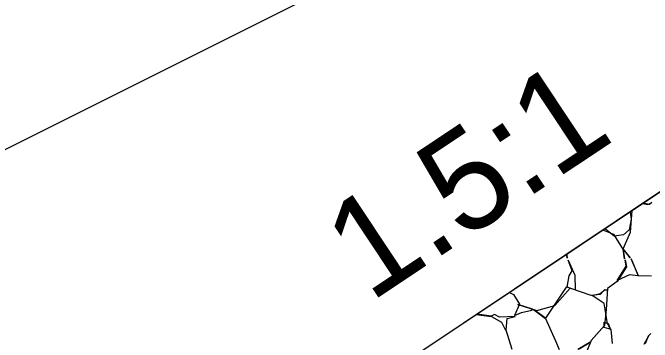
# Model space of a CAD drawing. Extents: x -26 to 2998798, y -429 to 819149.
# Drawn here: x 251.89 to 258.31, y 2039.34 to 2042.64 of the extents above; entities that cross this region are included whole.
import ezdxf

# ---------------------------------------------------------------- set-up
doc = ezdxf.new("R2010")
doc.units = 0
for name, color, linetype in [('DESIGN - EARTHWORK - Shapes', 7, 'Continuous'), ('DESIGN - PROFILE - Patterning', 7, 'Continuous'), ('DESIGN - SCRATCH - User 2', 7, 'Continuous'), ('DESIGN - SCRATCH - User 3', 7, 'Continuous'), ('DESIGN - SCRATCH - User 4', 7, 'Continuous'), ('DESIGN - TYPICAL - Finished Grade and Subgrade', 7, 'Continuous'), ('DESIGN - TYPICAL - Finished Grade Slopes Text', 7, 'Continuous')]:
    doc.layers.add(name, color=color, linetype=linetype)

msp = doc.modelspace()

# ---------------------------------------------------------------- linework, layer by layer
at = {"layer": 'DESIGN - EARTHWORK - Shapes'}
msp.add_lwpolyline([(300, 2056.0783), (299.2449, 2056.0632), (289, 2055.8583), (280.6596, 2055.6915), (236.27, 2026.0985), (247.7146, 2028.6577), (250.1042, 2028.9885), (255.4266, 2030.1126), (263.9312, 2032.5208), (268.2871, 2033.7542), (277.5839, 2036.1115), (286.7578, 2039.5231), (290.5851, 2040.9483), (292.2962, 2041.3689), (299.2394, 2040.0629), (300, 2040.0056)], dxfattribs=at)
at = {"layer": 'DESIGN - PROFILE - Patterning'}
for points in [[(258.2138, 2040.7276), (258.2669, 2040.7195), (258.3069, 2040.7395), (258.2819, 2040.7195), (258.22, 2040.7318)], [(257.8143, 2040.4613), (257.8369, 2040.4545), (257.9219, 2040.4195), (258.0169, 2040.2645), (258.0319, 2040.1745), (258.0169, 2040.2695), (258.0869, 2040.1845), (258.0169, 2040.2745), (258.0919, 2040.4395), (258.1094, 2040.6581)], [(258.0864, 2040.6427), (258.0969, 2040.5695), (258.0769, 2040.4645), (258.0219, 2040.4145), (257.9269, 2040.3995), (257.8419, 2040.4695), (257.8301, 2040.4719)], [(257.4481, 2040.2172), (257.4519, 2040.2145), (257.4569, 2040.1795), (257.4519, 2040.2095), (257.4454, 2040.2154)], [(257.9119, 2039.3245), (257.8969, 2039.4645), (257.8269, 2039.4845), (257.8269, 2039.5395), (257.8669, 2039.5245), (257.8919, 2039.4645), (257.8619, 2039.5245), (257.8269, 2039.7245), (257.7069, 2039.8045), (257.7869, 2039.8245), (257.8369, 2039.8645), (257.8619, 2039.8595), (257.8269, 2039.8595), (257.7869, 2039.8145), (257.6969, 2039.8045), (257.4919, 2039.8745), (257.4569, 2039.8895), (257.4769, 2040.0045), (257.5069, 2040.0545), (257.4669, 2040.1595), (257.5319, 2040.0095), (257.5369, 2039.8645)], [(258.3019, 2039.9995), (258.1719, 2040.0045), (258.0969, 2040.1745), (258.1669, 2040.0045), (258.0819, 2040.0145), (257.9569, 2039.9545), (258.0469, 2040.0995), (258.0369, 2040.1645), (258.0519, 2040.0945), (257.9569, 2039.9445), (257.8619, 2039.8745), (257.8469, 2039.6645), (257.8319, 2039.5045), (257.6969, 2039.3545), (257.6219, 2039.1745)], [(256.8752, 2039.8353), (256.9169, 2039.8145), (256.9769, 2039.7195), (256.9269, 2039.6045), (256.9969, 2039.6345), (257.1019, 2039.6595), (257.1069, 2039.6695), (256.9619, 2039.7145), (257.1519, 2039.6545), (257.3319, 2039.7045), (257.4869, 2039.8795), (257.4469, 2039.8895), (257.2369, 2039.5795), (257.1169, 2039.6645), (257.2369, 2039.5745), (257.3369, 2039.3495), (257.3769, 2039.2645)], [(256.5434, 2039.6141), (256.6969, 2039.5945), (256.7969, 2039.5395), (256.8369, 2039.4595)], [(256.9019, 2039.2645), (256.8419, 2039.4595), (256.8519, 2039.5745), (256.9319, 2039.5945), (256.7769, 2039.5895), (256.7269, 2039.6145), (256.6919, 2039.5995), (256.551, 2039.6191)], [(258.2419, 2039.3245), (258.2719, 2039.3995), (258.2969, 2039.4245), (258.2769, 2039.4045), (258.2269, 2039.3145)], [(257.5769, 2039.2695), (257.6919, 2039.3395), (257.5619, 2039.2645)]]:
    msp.add_lwpolyline(points, dxfattribs=at)
at = {"layer": 'DESIGN - SCRATCH - User 2'}
msp.add_lwpolyline([(299.2449, 2056.0632), (289, 2055.8583), (280.6596, 2055.6915), (236.27, 2026.0985), (239.4407, 2026.8075), (247.7146, 2028.6577), (250.1042, 2028.9885), (255.4266, 2030.1126), (263.9312, 2032.5208)], close=True, dxfattribs=at)
at = {"layer": 'DESIGN - SCRATCH - User 3'}
msp.add_lwpolyline([(236.27, 2026.0985), (254.2978, 2026.0985), (299.2449, 2056.0632), (280.6596, 2055.6915)], close=True, dxfattribs=at)
at = {"layer": 'DESIGN - SCRATCH - User 4'}
msp.add_line((280.6596, 2055.6915), (220.5, 2025.6117), dxfattribs=at)
at = {"layer": 'DESIGN - TYPICAL - Finished Grade and Subgrade'}
msp.add_line((280.6596, 2055.6915), (236.27, 2026.0985), dxfattribs=at)

# ---------------------------------------------------------------- texts
at = {"layer": 'DESIGN - TYPICAL - Finished Grade Slopes Text'}
msp.add_text('1.5:1', height=1, rotation=33.59628, dxfattribs=at).set_placement((255.4758, 2039.7297))

doc.saveas('drawing.dxf')
